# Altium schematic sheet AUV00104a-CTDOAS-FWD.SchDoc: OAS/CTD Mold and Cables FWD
size Tabloid; Organization: Monterey Bay Aquarium Research Institute; Address1: 7700 Sandholdt Rd; Address2: Moss Landing, CA 95039-9644; DocumentNumber: AUV00104; Revision: 1; SheetNumber: 1; SheetTotal: 1; CompanyName: MBARI; Engineer: Mark Sibenac
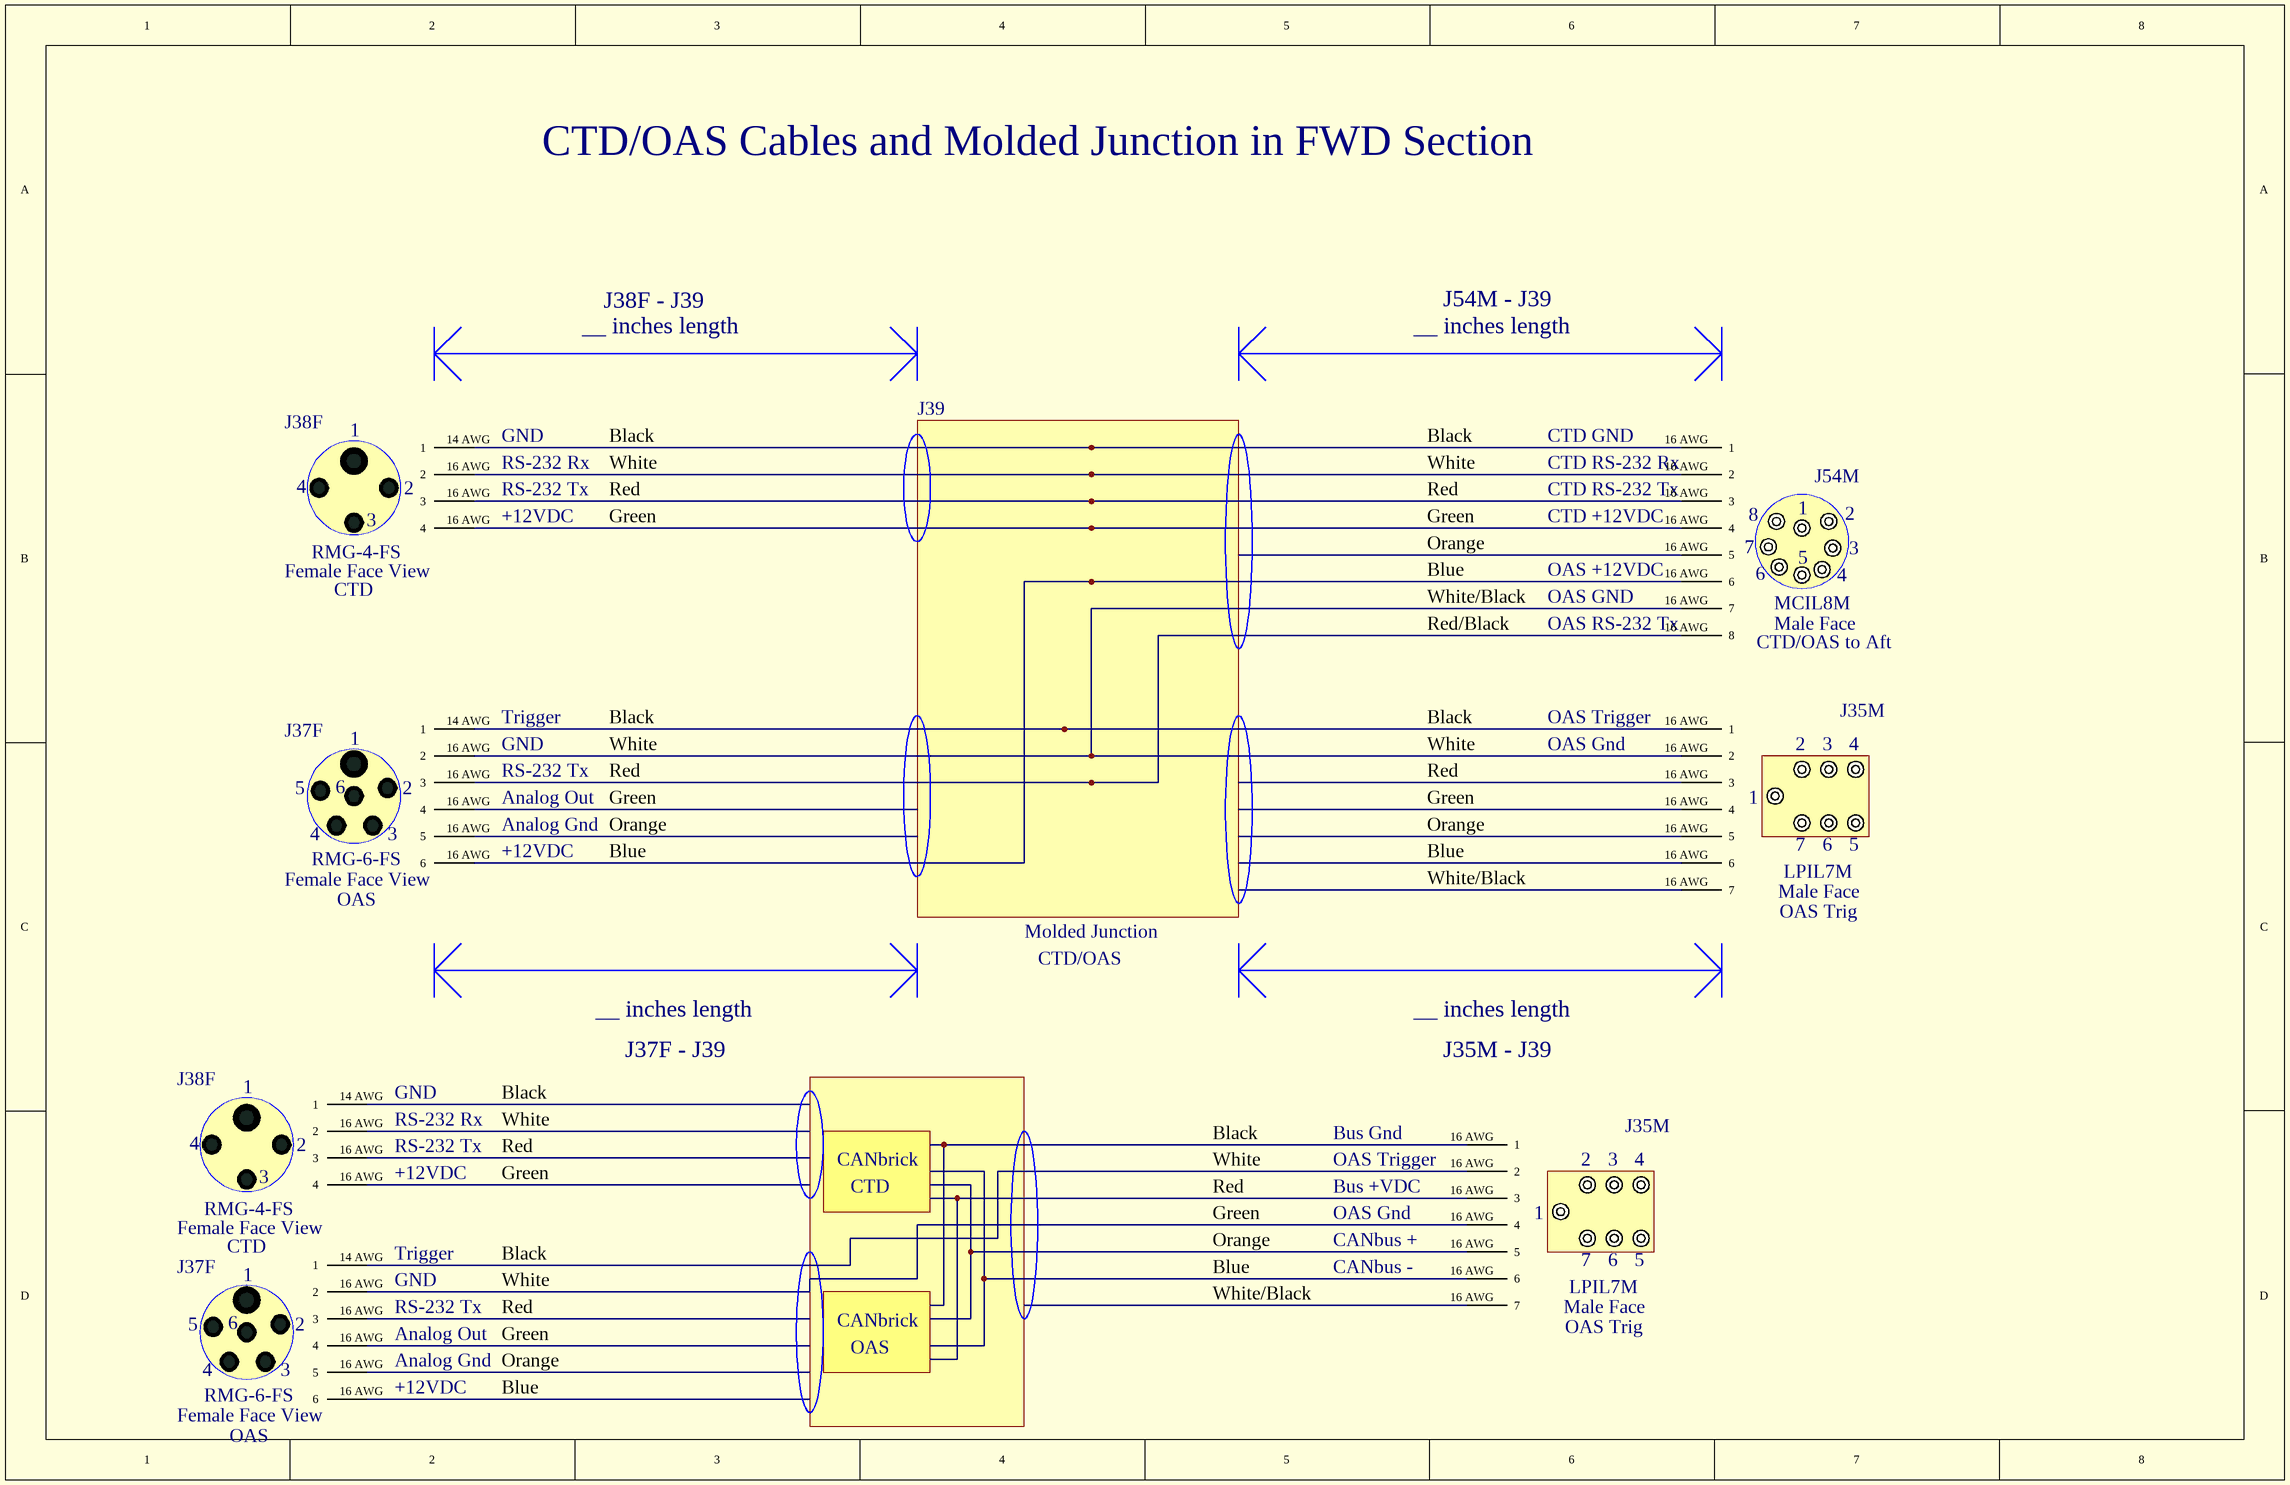
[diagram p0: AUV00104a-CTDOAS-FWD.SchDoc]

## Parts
(Parts that share a designator on the sheet are numbered #1, #2 ... from top to bottom, then left to right.)
J35M#1  LPIL7M  View: Male Face  DescSheet: OAS Trig
J35M#2  LPIL7M  View: Male Face  DescSheet: OAS Trig
J37F#1  RMG-6-FS  DescSheet: OAS
J37F#2  RMG-6-FS  DescSheet: OAS
J38F#1  RMG-4-FS  DescSheet: CTD
J38F#2  RMG-4-FS  DescSheet: CTD
J54M  MCIL8M  DescSheet: CTD/OAS to Aft  View: Male Face

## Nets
NetJ35M#1_16 AWG: J35M#1.16_AWG(1) J37F#1.14_AWG(1)
NetJ35M#1_16 AWG: J35M#1.16_AWG(2) J37F#1.16_AWG(2) J54M.16_AWG(7)  [a separate net that carries the same name]
NetJ35M#2_16 AWG: J35M#2.16_AWG(1) J37F#2.14_AWG(1)
NetJ35M#2_16 AWG: J35M#2.16_AWG(4) J37F#2.16_AWG(2)  [a separate net that carries the same name]
NetJ37F#1_16 AWG: J37F#1.16_AWG(3) J54M.16_AWG(8)
NetJ37F#1_16 AWG: J37F#1.16_AWG(6) J54M.16_AWG(6)  [a separate net that carries the same name]
NetJ38F#1_14 AWG: J38F#1.14_AWG(1) J54M.16_AWG(1)
NetJ38F#1_16 AWG: J38F#1.16_AWG(2) J54M.16_AWG(2)
NetJ38F#1_16 AWG: J38F#1.16_AWG(3) J54M.16_AWG(3)  [a separate net that carries the same name]
NetJ38F#1_16 AWG: J38F#1.16_AWG(4) J54M.16_AWG(4)  [a separate net that carries the same name]

Not connected (* = marked no-connect by the designer): J38F#2 14 AWG(1) 16 AWG(2)

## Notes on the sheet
- CTD/OAS Cables and Molded Junction in FWD Section
- __ inches length
- J38F - J39
- J54M - J39
- J39
- GND
- RS-232 Rx
- RS-232 Tx
- Black
- White
- Red
- (near J54M) CTD RS-232 Rx
- (near J54M) CTD RS-232 Tx
- CTD GND
- +12VDC
- Green
- Orange
- CTD +12VDC
- Blue
- White/Black
- Red/Black
- OAS GND
- OAS +12VDC
- (near J54M) OAS RS-232 Tx
- Trigger
- OAS Trigger
- OAS Gnd
- Analog Out
- Analog Gnd
- Molded Junction
- CTD/OAS
- J37F - J39
- J35M - J39
- CANbrick
- Bus Gnd
- CTD
- Bus +VDC
- CANbus +
- CANbus -
- OAS

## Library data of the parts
J35M#1 J35M#2 = SUBCONN-LPXX7M: Subconn LPIL7M Connector
J37F#1 J37F#2 = IMPULSE-RMG-6-FS: Impulse RMG-6-FS Connector; View: Female Face
J38F#1 J38F#2 = IMPULSE-RMG-4-FS: Impulse RMG-4-FS Connector; View: Female Face
J54M = SUBCONN-MCxx8M: Subconn MCIL8M Connector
